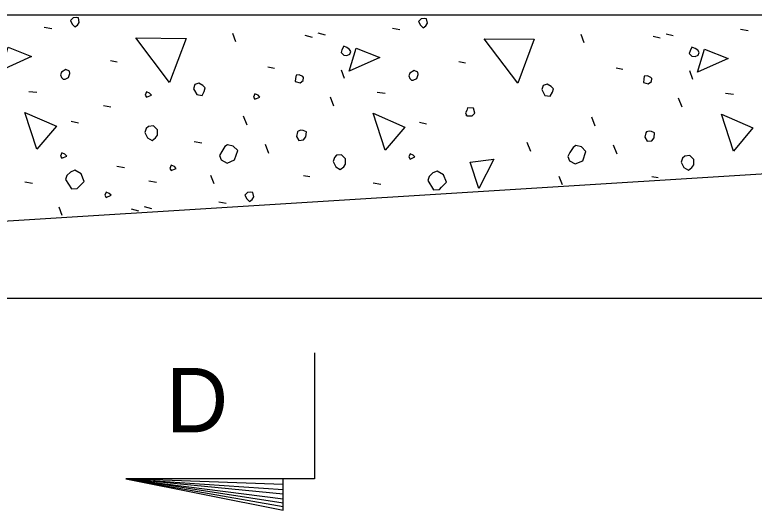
# Model space of a CAD drawing. Extents: x 1.5 to 68.7, y 0 to 31.1.
# Drawn here: x 28.438 to 31.375, y 8.892 to 10.859 of the extents above; entities that cross this region are included whole.
import ezdxf

# ---------------------------------------------------------------- set-up
doc = ezdxf.new("R2010")
doc.units = 0
for name, color, linetype in [('Dimension', 7, 'Continuous'), ('Miscellaneous', 7, 'Continuous'), ('TextStructures', 7, 'Continuous'), ('TrafBarrierConc', 7, 'Continuous')]:
    doc.layers.add(name, color=color, linetype=linetype)

msp = doc.modelspace()

# ---------------------------------------------------------------- linework, layer by layer
at = {"layer": 'Dimension'}
for p, q in [((29.503, 8.9937), (28.878, 9.0171)), ((28.878, 9.0171), (29.503, 8.9737)), ((29.503, 8.9554), (28.878, 9.0171)), ((28.878, 9.0171), (29.503, 8.9371)), ((29.503, 8.9204), (28.878, 9.0171)), ((28.878, 9.0171), (29.503, 8.9071))]:
    msp.add_line(p, q, dxfattribs=at)
msp.add_lwpolyline([(29.628, 9.5171), (29.628, 9.0171), (28.878, 9.0171), (29.503, 8.8921), (29.503, 9.0171)], dxfattribs=at)
at = {"layer": 'Miscellaneous'}
for p, q in [((28.554, 10.81), (28.5841, 10.8047)), ((29.3159, 10.7517), (29.3035, 10.7852)), ((29.6416, 10.7875), (29.6699, 10.7804)), ((29.9373, 10.8065), (29.9673, 10.8012)), ((30.6992, 10.7481), (30.6868, 10.7817)), ((31.0249, 10.7839), (31.0532, 10.7768)), ((31.3206, 10.8029), (31.3506, 10.7976)), ((29.5899, 10.7782), (29.6182, 10.7711)), ((30.9732, 10.7746), (31.0015, 10.7676)), ((28.8174, 10.6774), (28.8439, 10.6721)), ((30.2007, 10.6739), (30.2272, 10.6686)), ((29.4432, 10.6527), (29.4697, 10.6474)), ((29.7477, 10.6063), (29.7353, 10.6398)), ((30.8265, 10.6491), (30.853, 10.6438)), ((31.131, 10.6027), (31.1186, 10.6363)), ((28.4939, 10.5554), (28.5257, 10.5519)), ((29.8772, 10.5519), (29.909, 10.5484)), ((31.2605, 10.5484), (31.2923, 10.5448)), ((29.7053, 10.4967), (29.6911, 10.532)), ((31.0885, 10.4931), (31.0744, 10.5285)), ((28.7893, 10.4998), (28.8194, 10.4945)), ((29.3601, 10.4211), (29.346, 10.4564)), ((28.6618, 10.437), (28.6901, 10.4299)), ((30.0451, 10.4335), (30.0734, 10.4264)), ((30.7434, 10.4175), (30.7292, 10.4529)), ((29.1503, 10.3562), (29.1803, 10.3509)), ((29.4472, 10.3093), (29.433, 10.3446)), ((30.4871, 10.3168), (30.4729, 10.3521)), ((30.8304, 10.3057), (30.8163, 10.3411)), ((28.8426, 10.2577), (28.8727, 10.2524)), ((29.2293, 10.1877), (29.2169, 10.2213)), ((28.4775, 10.1961), (28.5076, 10.1908)), ((28.9698, 10.2002), (28.9998, 10.1949)), ((29.585, 10.2209), (29.6098, 10.2173)), ((29.8608, 10.1926), (29.8909, 10.1873)), ((30.6126, 10.1842), (30.6002, 10.2178)), ((30.9683, 10.2173), (30.9931, 10.2138)), ((29.2474, 10.1166), (29.2775, 10.1113)), ((28.626, 10.0618), (28.6137, 10.0954)), ((28.9, 10.0883), (28.9283, 10.0812)), ((28.9517, 10.0976), (28.98, 10.0905))]:
    msp.add_line(p, q, dxfattribs=at)
for points in [[(28.6654, 10.8224), (28.676, 10.8118), (28.6866, 10.8188), (28.6937, 10.8294), (28.6901, 10.8471), (28.6813, 10.8489), (28.6689, 10.8471), (28.6583, 10.8365), (28.6654, 10.8224)], [(30.0486, 10.8188), (30.0593, 10.8082), (30.0699, 10.8153), (30.0769, 10.8259), (30.0734, 10.8436), (30.0646, 10.8453), (30.0522, 10.8436), (30.0416, 10.833), (30.0486, 10.8188)], [(29.0525, 10.5908), (28.9182, 10.7676), (29.1179, 10.7658), (29.0525, 10.5908)], [(30.4358, 10.5873), (30.3014, 10.764), (30.5012, 10.7623), (30.4358, 10.5873)], [(28.3825, 10.6385), (28.4108, 10.7304), (28.5045, 10.6933), (28.3825, 10.6385)], [(29.7441, 10.6991), (29.7565, 10.6973), (29.7689, 10.7026), (29.7724, 10.7132), (29.7671, 10.722), (29.7565, 10.7291), (29.7441, 10.7344), (29.7371, 10.7203), (29.7335, 10.7097), (29.7441, 10.6991)], [(29.7658, 10.635), (29.7941, 10.7269), (29.8878, 10.6898), (29.7658, 10.635)], [(31.1274, 10.6955), (31.1398, 10.6938), (31.1522, 10.6991), (31.1557, 10.7097), (31.1504, 10.7185), (31.1398, 10.7256), (31.1274, 10.7309), (31.1204, 10.7167), (31.1168, 10.7061), (31.1274, 10.6955)], [(31.1491, 10.6314), (31.1774, 10.7234), (31.2711, 10.6862), (31.1491, 10.6314)], [(28.63, 10.6032), (28.6371, 10.6032), (28.6512, 10.6102), (28.6565, 10.6261), (28.6548, 10.635), (28.6406, 10.6421), (28.6229, 10.6314), (28.6194, 10.6208), (28.6229, 10.6102), (28.63, 10.6032)], [(30.0133, 10.5996), (30.0204, 10.5996), (30.0345, 10.6067), (30.0398, 10.6226), (30.038, 10.6314), (30.0239, 10.6385), (30.0062, 10.6279), (30.0027, 10.6173), (30.0062, 10.6067), (30.0133, 10.5996)], [(29.551, 10.5943), (29.5705, 10.589), (29.5828, 10.5979), (29.5846, 10.6102), (29.5811, 10.6138), (29.5669, 10.6208), (29.5546, 10.6191), (29.5528, 10.6067), (29.551, 10.5943)], [(30.9343, 10.5908), (30.9537, 10.5855), (30.9661, 10.5943), (30.9679, 10.6067), (30.9643, 10.6102), (30.9502, 10.6173), (30.9378, 10.6155), (30.9361, 10.6032), (30.9343, 10.5908)], [(29.1515, 10.559), (29.1603, 10.5431), (29.1816, 10.5395), (29.1904, 10.5554), (29.1939, 10.5696), (29.1851, 10.5784), (29.1692, 10.5873), (29.1533, 10.582), (29.148, 10.566), (29.1515, 10.559)], [(30.5348, 10.5554), (30.5436, 10.5395), (30.5648, 10.536), (30.5737, 10.5519), (30.5772, 10.566), (30.5684, 10.5749), (30.5525, 10.5837), (30.5366, 10.5784), (30.5312, 10.5625), (30.5348, 10.5554)], [(28.9606, 10.532), (28.9801, 10.5408), (28.973, 10.5479), (28.9606, 10.5532), (28.9553, 10.5408), (28.9606, 10.532)], [(29.3914, 10.5238), (29.4108, 10.5326), (29.4037, 10.5397), (29.3914, 10.545), (29.3861, 10.5326), (29.3914, 10.5238)], [(30.2325, 10.4582), (30.2537, 10.4582), (30.2643, 10.4688), (30.259, 10.4883), (30.236, 10.49), (30.2325, 10.4794), (30.2272, 10.4706), (30.2325, 10.4582), (30.229, 10.4617)], [(28.5253, 10.3252), (28.4775, 10.4719), (28.6031, 10.4171), (28.5253, 10.3252)], [(29.9086, 10.3216), (29.8608, 10.4684), (29.9863, 10.4136), (29.9086, 10.3216)], [(31.2918, 10.3181), (31.2441, 10.4648), (31.3696, 10.41), (31.2918, 10.3181)], [(28.9543, 10.3918), (28.9649, 10.3706), (28.9826, 10.36), (28.9967, 10.3706), (29.0038, 10.3812), (29.0038, 10.4024), (28.9879, 10.4183), (28.9684, 10.4165), (28.9596, 10.4077), (28.9543, 10.3918)], [(29.5568, 10.3764), (29.5656, 10.3605), (29.585, 10.3623), (29.5939, 10.3747), (29.5957, 10.3941), (29.5833, 10.3994), (29.5744, 10.4012), (29.5638, 10.3977), (29.5603, 10.3941), (29.5568, 10.3764)], [(30.94, 10.3729), (30.9489, 10.357), (30.9683, 10.3588), (30.9772, 10.3711), (30.9789, 10.3906), (30.9666, 10.3959), (30.9577, 10.3977), (30.9471, 10.3941), (30.9436, 10.3906), (30.94, 10.3729)], [(29.2576, 10.2832), (29.2806, 10.2708), (29.3106, 10.2832), (29.323, 10.3203), (29.3053, 10.338), (29.2823, 10.3433), (29.2717, 10.3362), (29.2593, 10.3168), (29.2505, 10.3009), (29.2576, 10.2832)], [(30.6408, 10.2797), (30.6638, 10.2673), (30.6939, 10.2797), (30.7063, 10.3168), (30.6886, 10.3345), (30.6656, 10.3398), (30.655, 10.3327), (30.6426, 10.3132), (30.6338, 10.2973), (30.6408, 10.2797)], [(28.6243, 10.2898), (28.6437, 10.2987), (28.6366, 10.3057), (28.6243, 10.311), (28.619, 10.2987), (28.6243, 10.2898)], [(29.7017, 10.2775), (29.7123, 10.2562), (29.73, 10.2456), (29.7441, 10.2562), (29.7512, 10.2668), (29.7512, 10.2881), (29.7353, 10.304), (29.7159, 10.3022), (29.707, 10.2934), (29.7017, 10.2775)], [(30.0075, 10.2863), (30.027, 10.2951), (30.0199, 10.3022), (30.0075, 10.3075), (30.0022, 10.2951), (30.0075, 10.2863)], [(30.2802, 10.1701), (30.2466, 10.2744), (30.3403, 10.2867), (30.2802, 10.1701)], [(31.085, 10.2739), (31.0956, 10.2527), (31.1133, 10.2421), (31.1274, 10.2527), (31.1345, 10.2633), (31.1345, 10.2845), (31.1186, 10.3004), (31.0991, 10.2987), (31.0903, 10.2898), (31.085, 10.2739)], [(29.0591, 10.2406), (29.0785, 10.2494), (29.0715, 10.2565), (29.0591, 10.2618), (29.0538, 10.2494), (29.0591, 10.2406)], [(28.6393, 10.205), (28.6623, 10.1679), (28.6852, 10.1696), (28.6941, 10.1785), (28.7135, 10.1979), (28.7012, 10.228), (28.6764, 10.2421), (28.6587, 10.235), (28.6446, 10.2209), (28.6393, 10.205)], [(30.0783, 10.2014), (30.1012, 10.1643), (30.1242, 10.1661), (30.1331, 10.1749), (30.1525, 10.1944), (30.1401, 10.2244), (30.1154, 10.2386), (30.0977, 10.2315), (30.0836, 10.2173), (30.0783, 10.2014)], [(28.8007, 10.1339), (28.8201, 10.1427), (28.813, 10.1498), (28.8007, 10.1551), (28.7954, 10.1427), (28.8007, 10.1339)], [(29.3588, 10.129), (29.3694, 10.1184), (29.38, 10.1254), (29.3871, 10.136), (29.3835, 10.1537), (29.3747, 10.1555), (29.3623, 10.1537), (29.3517, 10.1431), (29.3588, 10.129)]]:
    msp.add_lwpolyline(points, dxfattribs=at)
at = {"layer": 'TrafBarrierConc'}
for p, q in [((28.2772, 10.8595), (34.2217, 10.8595)), ((27.4971, 9.9844), (31.4971, 10.2344)), ((27.4971, 9.7345), (36.6763, 9.7345))]:
    msp.add_line(p, q, dxfattribs=at)

# ---------------------------------------------------------------- texts
at = {"layer": 'TextStructures'}
msp.add_text('D', height=0.256, dxfattribs=at).set_placement((29.0376, 9.2014))

doc.saveas('drawing.dxf')
